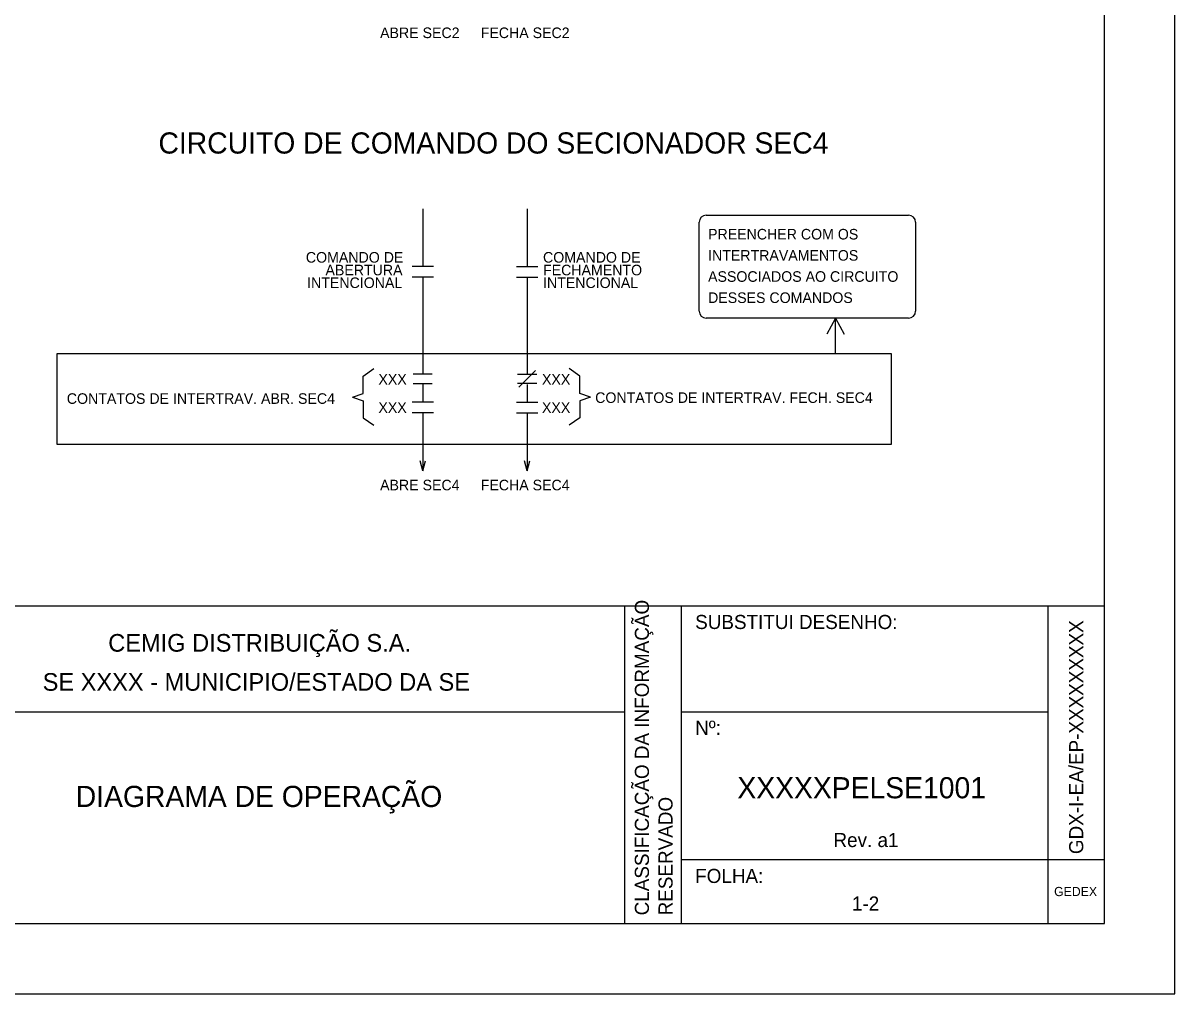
# Model space of a CAD drawing. Extents: x 501 to 1404, y 358 to 952.
# Drawn here: x 1240.3 to 1403.6, y 358 to 495.6 of the extents above; entities that cross this region are included whole.
import ezdxf

# ---------------------------------------------------------------- set-up
doc = ezdxf.new("R2010")
doc.units = 0
doc.layers.add('New Level (0)', color=7, linetype='Continuous')

msp = doc.modelspace()

# ---------------------------------------------------------------- linework, layer by layer
for p, q in [((1296.98, 469.25), (1296.98, 461.08)), ((1311.77, 469.25), (1311.77, 461.08)), ((1298.48, 461.08), (1295.48, 461.08)), ((1310.27, 461.08), (1313.27, 461.08)), ((1298.48, 459.58), (1295.48, 459.58)), ((1296.98, 459.58), (1296.98, 445.84)), ((1310.27, 459.58), (1313.27, 459.58)), ((1311.77, 459.58), (1311.77, 445.84)), ((1288.52, 445.52), (1290.02, 446.6)), ((1298.33, 445.84), (1295.63, 445.84)), ((1310.42, 445.84), (1313.12, 445.84)), ((1310.58, 443.97), (1312.97, 446.36)), ((1319.24, 445.52), (1317.74, 446.6)), ((1288.52, 443.06), (1288.52, 445.52)), ((1295.63, 444.49), (1298.33, 444.49)), ((1296.98, 444.34), (1296.98, 441.83)), ((1313.12, 444.49), (1310.42, 444.49)), ((1311.77, 444.34), (1311.77, 441.83)), ((1319.24, 443.06), (1319.24, 445.52)), ((1287.02, 442.56), (1288.52, 443.06)), ((1287.02, 442.56), (1288.52, 442.06)), ((1320.74, 442.56), (1319.24, 443.06)), ((1320.74, 442.56), (1319.24, 442.06)), ((1288.52, 442.06), (1288.52, 439.65)), ((1298.48, 441.83), (1295.48, 441.83)), ((1310.27, 441.83), (1313.27, 441.83)), ((1319.24, 442.06), (1319.24, 439.65)), ((1288.52, 439.65), (1290.02, 438.57)), ((1298.48, 440.33), (1295.48, 440.33)), ((1296.98, 440.33), (1296.98, 432.1)), ((1310.27, 440.33), (1313.27, 440.33)), ((1311.77, 440.33), (1311.77, 432.1)), ((1319.24, 439.65), (1317.74, 438.57)), ((1296.98, 432.1), (1296.59, 433.55)), ((1296.98, 432.1), (1297.37, 433.55)), ((1311.77, 432.1), (1311.38, 433.55)), ((1311.77, 432.1), (1312.16, 433.55))]:
    msp.add_line(p, q)
at = {"layer": 'New Level (0)'}
for p, q in [((1403.58, 357.96), (1403.58, 951.96)), ((1403.58, 357.96), (1403.58, 951.96)), ((1393.58, 367.96), (1393.58, 941.96)), ((1393.58, 367.96), (1393.58, 941.96)), ((1336.14, 454.77), (1336.14, 467.35)), ((1337.14, 468.35), (1365.82, 468.35)), ((1366.82, 467.35), (1366.82, 454.77)), ((1365.82, 453.77), (1337.14, 453.77)), ((1355.47, 453.77), (1354.26, 451.47)), ((1355.47, 448.74), (1355.47, 453.77)), ((1355.47, 453.77), (1356.68, 451.47)), ((572.58, 412.96), (1393.58, 412.96)), ((1325.58, 412.96), (1325.58, 367.96)), ((1333.58, 412.96), (1333.58, 367.96)), ((1385.58, 412.96), (1385.58, 367.96)), ((1143.58, 397.96), (1325.58, 397.96)), ((1333.58, 397.96), (1385.58, 397.96)), ((1393.58, 376.96), (1333.58, 376.96)), ((572.58, 367.96), (1393.58, 367.96)), ((572.58, 367.96), (1393.58, 367.96)), ((562.58, 357.96), (1403.58, 357.96)), ((562.58, 357.96), (1403.58, 357.96))]:
    msp.add_line(p, q, dxfattribs=at)
msp.add_lwpolyline([(1245.17, 448.74), (1363.37, 448.74), (1363.37, 435.85), (1245.17, 435.85)], close=True, dxfattribs=at)
for centre, start, end in [((1337.14, 467.35), 90, 180), ((1365.82, 467.35), 0, 90), ((1337.14, 454.77), 180, 270), ((1365.82, 454.77), 270, 0)]:
    msp.add_arc(centre, 1, start, end, dxfattribs=at)

# ---------------------------------------------------------------- texts
for s, height, p in [('ABRE SEC2', 1.5, (1290.93, 493.46)), ('FECHA SEC2', 1.5, (1305.19, 493.46)), ('CIRCUITO DE COMANDO DO SECIONADOR SEC4', 3, (1259.52, 477.09)), ('PREENCHER COM OS ', 1.5, (1337.41, 464.91)), ('COMANDO DE', 1.5, (1280.41, 461.63)), ('COMANDO DE ', 1.5, (1314.02, 461.63)), ('INTERTRAVAMENTOS', 1.5, (1337.41, 461.91)), (' ABERTURA', 1.5, (1282.63, 459.83)), ('FECHAMENTO ', 1.5, (1314.02, 459.83)), ('ASSOCIADOS AO CIRCUITO ', 1.5, (1337.41, 458.91)), (' INTENCIONAL', 1.5, (1280.03, 458.03)), ('INTENCIONAL', 1.5, (1314.02, 458.03)), ('DESSES COMANDOS', 1.5, (1337.41, 455.91)), ('XXX', 1.5, (1290.69, 444.34)), ('XXX', 1.5, (1313.87, 444.34)), ('CONTATOS DE INTERTRAV. ABR. SEC4', 1.5, (1246.53, 441.61)), ('CONTATOS DE INTERTRAV. FECH. SEC4', 1.5, (1321.41, 441.74)), ('XXX', 1.5, (1290.69, 440.33)), ('XXX', 1.5, (1313.87, 440.33)), ('ABRE SEC4', 1.5, (1290.93, 429.35)), ('FECHA SEC4', 1.5, (1305.19, 429.35))]:
    msp.add_text(s, height=height).set_placement(p)
for s, p in [('CLASSIFICAÇÃO DA INFORMAÇÃO', (1329.03, 369.1)), ('GDX-I-EA/EP-XXXXXXXXX', (1390.58, 377.78)), ('RESERVADO', (1332.38, 369.1))]:
    msp.add_text(s, height=2, rotation=90, dxfattribs=at).set_placement(p)
for s, height, p in [('SUBSTITUI DESENHO:', 2, (1335.58, 409.69)), ('CEMIG DISTRIBUIÇÃO S.A.', 2.5, (1252.4, 406.48)), ('SE XXXX - MUNICIPIO/ESTADO DA SE', 2.5, (1243.11, 400.94)), ('Nº:', 2, (1335.58, 394.69)), ('XXXXXPELSE1001', 3, (1341.56, 385.69)), ('DIAGRAMA DE OPERAÇÃO', 3, (1247.8, 384.46)), ('Rev. a1', 2, (1355.18, 378.78)), ('FOLHA:', 2, (1335.58, 373.69)), ('GEDEX', 1.3, (1386.45, 371.83)), ('1-2', 2, (1357.8, 369.78))]:
    msp.add_text(s, height=height, dxfattribs=at).set_placement(p)

doc.saveas('drawing.dxf')
